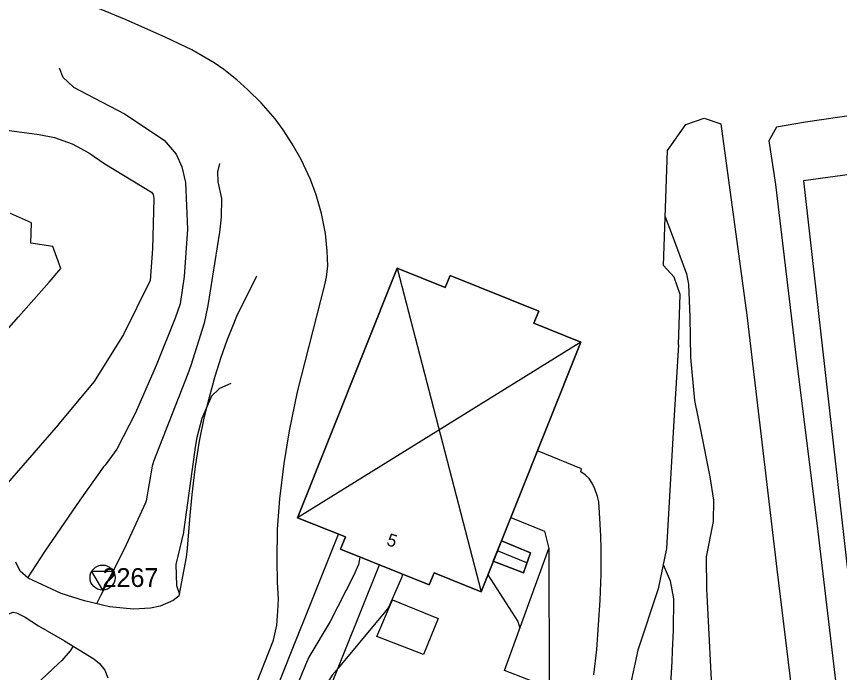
# Model space of a CAD drawing. Extents: x 67169 to 69652, y 20189 to 22818.
# Drawn here: x 69362.6 to 69428.4, y 21264.9 to 21317.2 of the extents above; entities that cross this region are included whole.
import ezdxf

# ---------------------------------------------------------------- set-up
doc = ezdxf.new("R2010")
doc.units = 0
for name, color, linetype in [('BYGGNAD_HUSLIV', 7, 'Continuous'), ('BYGGNAD_HUSLIV 11', 7, 'Continuous'), ('BYGGNADSSYMBOLER', 7, 'Continuous'), ('BYGGNADSSYMBOLER 30', 7, 'Continuous'), ('HOJDKURVOR_2014', 7, 'Continuous'), ('HOJDKURVOR_2014 5M', 7, 'Continuous'), ('Instruktioner', 7, 'Continuous'), ('MUR_STAKET', 7, 'Continuous'), ('MUR_STAKET_SYMBOL', 7, 'Continuous'), ('Std_Ritningsstämpel', 7, 'Continuous'), ('STOMPUNKTER', 7, 'Continuous'), ('STOMPUNKTER TEXT', 7, 'Continuous'), ('VAGAR 121', 7, 'Continuous'), ('VAGAR 123', 7, 'Continuous')]:
    doc.layers.add(name, color=color, linetype=linetype)

msp = doc.modelspace()

# ---------------------------------------------------------------- linework, layer by layer
at = {"layer": 'BYGGNAD_HUSLIV'}
for points in [[(69393.045, 21297.137), (69396.867, 21295.597), (69397.259, 21296.571), (69404.346, 21293.717), (69403.954, 21292.742), (69407.707, 21291.231), (69399.739, 21271.323), (69395.986, 21272.834), (69395.594, 21271.861), (69388.506, 21274.714), (69388.899, 21275.688), (69385.077, 21277.228), (69393.045, 21297.137)], [(69400.711, 21273.753), (69401.368, 21275.394), (69403.69, 21274.419), (69403.113, 21272.833), (69400.711, 21273.753)]]:
    msp.add_lwpolyline(points, dxfattribs=at)
at = {"layer": 'BYGGNAD_HUSLIV 11'}
msp.add_lwpolyline([(69393.045, 21297.137), (69396.867, 21295.597), (69397.259, 21296.571), (69404.346, 21293.717), (69403.954, 21292.742), (69407.707, 21291.231), (69399.739, 21271.323), (69395.986, 21272.834), (69395.594, 21271.861), (69388.506, 21274.714), (69388.899, 21275.688), (69385.077, 21277.228), (69393.045, 21297.137)], dxfattribs=at)
at = {"layer": 'BYGGNADSSYMBOLER'}
for p, q in [((69393.045, 21297.137), (69399.739, 21271.323)), ((69407.707, 21291.231), (69385.077, 21277.228)), ((69403.401, 21273.626), (69401.04, 21274.573))]:
    msp.add_line(p, q, dxfattribs=at)
at = {"layer": 'BYGGNADSSYMBOLER 30'}
for p, q in [((69393.045, 21297.137), (69399.739, 21271.323)), ((69407.707, 21291.231), (69385.077, 21277.228))]:
    msp.add_line(p, q, dxfattribs=at)
at = {"layer": 'HOJDKURVOR_2014'}
for points in [[(69366.062, 21313.148), (69366.332, 21312.38), (69367.183, 21311.587), (69368.875, 21310.704), (69371.275, 21309.469), (69374.422, 21307.369), (69375.396, 21306.253), (69375.858, 21305.221), (69376.147, 21303.984), (69376.289, 21300.262), (69376.042, 21296.479), (69375.707, 21294.299), (69375.323, 21293.164), (69373.805, 21289.375), (69372.142, 21285.594), (69370.649, 21282.69), (69369.713, 21281.421), (69369.603, 21281.289), (69367.704, 21278.629), (69364.915, 21274.561), (69363.536, 21272.425)], [(69378.863, 21305.507), (69378.681, 21304.824), (69378.719, 21304.04), (69379.016, 21302.704), (69378.993, 21301.226), (69378.841, 21300.023), (69377.914, 21294.162), (69377.639, 21292.766), (69376.567, 21289.372), (69376.315, 21288.705), (69373.596, 21281.719), (69373.464, 21281.331), (69373.004, 21278.561), (69372.954, 21278.402), (69371.228, 21274.711), (69369.385, 21271.032), (69369.027, 21270.352)], [(69379.75, 21287.952), (69378.854, 21287.534), (69378.205, 21286.934), (69377.45, 21285.136), (69377.054, 21283.621), (69376.915, 21282.849), (69376.856, 21282.461), (69375.98, 21276.098), (69375.969, 21276.054), (69375.358, 21273.493), (69375.429, 21271.806), (69375.669, 21271.128)], [(69390.056, 21274.09), (69389.939, 21273.486), (69389.547, 21272.582), (69387.675, 21268.953), (69385.976, 21266.085), (69385.71, 21265.48), (69383.133, 21259.153), (69382.74, 21258.152)], [(69414.284, 21273.49), (69414.846, 21272.202), (69415.096, 21270.761), (69415.066, 21268.26), (69414.999, 21266.593), (69414.956, 21265.759), (69414.698, 21261.223)], [(69400.282, 21272.679), (69402.666, 21268.945), (69402.835, 21268.423)], [(69367.175, 21266.967), (69366.936, 21266.605), (69366.257, 21265.822), (69366.009, 21265.58), (69363.704, 21263.443), (69362.278, 21262.161), (69359.337, 21259.705), (69357.821, 21258.53), (69354.449, 21255.997), (69353.343, 21255.257), (69350.982, 21254.075), (69348.891, 21253.425)]]:
    msp.add_lwpolyline(points, dxfattribs=at)
at = {"layer": 'HOJDKURVOR_2014 5M'}
for points in [[(69357.261, 21308.773), (69364.451, 21307.814), (69365.679, 21307.565), (69367.082, 21307.056), (69368.425, 21306.338), (69369.685, 21305.47), (69373.423, 21303.206), (69373.558, 21303.019), (69373.614, 21302.708), (69373.492, 21298.689), (69373.312, 21296.149), (69371.201, 21291.841), (69368.84, 21288.11), (69366.033, 21284.71), (69365.964, 21284.633), (69361.735, 21279.781)], [(69414.432, 21301.237), (69414.998, 21299.79), (69416.14, 21296.684), (69416.299, 21295.877), (69416.396, 21293.255), (69416.457, 21290.019), (69416.767, 21286.576), (69417.274, 21284.109), (69417.995, 21280.5), (69418.291, 21278.617), (69418.266, 21276.927), (69417.716, 21274.095), (69417.726, 21271.528), (69417.748, 21271.035), (69418.223, 21262.202)], [(69393.453, 21272.723), (69393.37, 21272.422), (69392.354, 21270.069), (69392.144, 21269.798), (69388.053, 21264.912), (69387.853, 21264.656), (69387.335, 21263.83), (69386.198, 21261.349), (69385.974, 21260.71), (69384.88, 21257.329)]]:
    msp.add_lwpolyline(points, dxfattribs=at)
at = {"layer": 'MUR_STAKET'}
for points in [[(69375.634, 21270.984), (69376.21, 21274.085), (69376.297, 21274.807), (69376.506, 21277.397), (69376.681, 21279.087), (69376.768, 21279.985), (69376.943, 21281.323), (69377.258, 21283.331), (69377.661, 21285.304), (69378.047, 21286.854), (69378.504, 21288.527), (69378.995, 21290.042), (69379.47, 21291.398), (69379.962, 21292.649), (69380.244, 21293.318), (69381.834, 21296.539)], [(69408.747, 21264.686), (69408.98, 21266.712), (69409.246, 21270.644), (69409.318, 21272.723), (69409.316, 21274.707), (69409.293, 21275.783), (69409.187, 21277.619), (69409.127, 21278.501), (69409.043, 21278.933), (69408.831, 21279.535), (69408.61, 21279.989), (69408.357, 21280.346), (69408.06, 21280.642), (69407.702, 21280.884), (69407.765, 21281.116), (69404.235, 21282.555)], [(69402.109, 21277.244), (69404.787, 21276.153), (69405.146, 21274.761), (69405.166, 21263.65)], [(69381.462, 21258.643), (69383.613, 21264.086), (69385.027, 21267.616), (69385.796, 21269.516), (69388.35, 21275.909)], [(69385.157, 21257.133), (69387.341, 21262.785), (69391.623, 21273.459)]]:
    msp.add_lwpolyline(points, dxfattribs=at)
at = {"layer": 'MUR_STAKET_SYMBOL'}
for p, q in [((69381.443, 21295.747), (69381.443, 21295.747)), ((69380.711, 21294.265), (69380.711, 21294.265)), ((69380.095, 21292.968), (69380.095, 21292.968)), ((69379.572, 21291.654), (69379.572, 21291.654)), ((69379.023, 21290.119), (69379.023, 21290.119)), ((69378.532, 21288.62), (69378.532, 21288.62)), ((69378.138, 21287.191), (69378.138, 21287.191)), ((69377.738, 21285.618), (69377.738, 21285.618)), ((69377.418, 21284.114), (69377.418, 21284.114)), ((69377.161, 21282.725), (69377.161, 21282.725)), ((69405.587, 21282.001), (69405.587, 21282.001)), ((69407.034, 21281.411), (69407.034, 21281.411)), ((69376.933, 21281.246), (69376.933, 21281.246)), ((69408.385, 21280.295), (69408.385, 21280.295)), ((69376.73, 21279.629), (69376.73, 21279.629)), ((69408.993, 21279.074), (69408.993, 21279.074)), ((69376.572, 21278.033), (69376.572, 21278.033)), ((69409.183, 21277.672), (69409.183, 21277.672)), ((69376.441, 21276.628), (69376.441, 21276.628)), ((69409.261, 21276.263), (69409.261, 21276.263)), ((69376.322, 21275.159), (69376.322, 21275.159)), ((69388.009, 21275.06), (69388.009, 21275.06)), ((69409.311, 21274.743), (69409.311, 21274.743)), ((69376.156, 21273.8), (69376.156, 21273.8)), ((69387.461, 21273.688), (69387.461, 21273.688)), ((69409.318, 21273.267), (69409.318, 21273.267)), ((69375.887, 21272.352), (69375.887, 21272.352)), ((69386.908, 21272.306), (69386.908, 21272.306)), ((69391.083, 21272.108), (69391.083, 21272.108)), ((69409.277, 21271.649), (69409.277, 21271.649)), ((69375.653, 21271.091), (69375.653, 21271.091)), ((69386.35, 21270.908), (69386.35, 21270.908)), ((69390.525, 21270.72), (69390.525, 21270.72)), ((69409.213, 21270.171), (69409.213, 21270.171)), ((69385.783, 21269.484), (69385.783, 21269.484)), ((69389.954, 21269.298), (69389.954, 21269.298)), ((69405.155, 21269.144), (69405.155, 21269.144)), ((69409.113, 21268.674), (69409.113, 21268.674)), ((69385.212, 21268.07), (69385.212, 21268.07)), ((69389.397, 21267.908), (69389.397, 21267.908)), ((69409.014, 21267.216), (69409.014, 21267.216)), ((69384.663, 21266.713), (69384.663, 21266.713)), ((69388.829, 21266.493), (69388.829, 21266.493)), ((69408.863, 21265.719), (69408.863, 21265.719)), ((69384.111, 21265.334), (69384.111, 21265.334)), ((69388.273, 21265.105), (69388.273, 21265.105))]:
    msp.add_line(p, q, dxfattribs=at)
at = {"layer": 'Std_Ritningsstämpel'}
for points in [[(69393.045, 21297.137), (69385.077, 21277.228), (69388.899, 21275.688), (69388.506, 21274.714), (69395.594, 21271.861), (69395.986, 21272.834), (69399.739, 21271.323), (69407.707, 21291.231), (69403.954, 21292.742), (69404.346, 21293.717), (69397.259, 21296.571), (69396.867, 21295.597)], [(69400.711, 21273.753), (69403.113, 21272.833), (69403.69, 21274.419), (69401.368, 21275.394)]]:
    msp.add_lwpolyline(points, close=True, dxfattribs=at)
at = {"layer": 'STOMPUNKTER'}
msp.add_lwpolyline([(69369.514, 21271.451), (69370.392, 21272.931), (69368.639, 21272.931)], close=True, dxfattribs=at)
msp.add_circle((69369.514, 21272.451), 1, dxfattribs=at)
at = {"layer": 'VAGAR 121'}
for points in [[(69379.822, 21258.929), (69383.159, 21267.446), (69383.43, 21268.647), (69383.52, 21269.757), (69383.564, 21270.732), (69383.495, 21272.092), (69383.448, 21273.837), (69383.491, 21276.307), (69383.671, 21278.732), (69384.009, 21281.566), (69384.436, 21284.15), (69385.069, 21287.278), (69387.259, 21295.802), (69387.395, 21296.436), (69387.508, 21297.32), (69387.461, 21298.499), (69387.324, 21299.904), (69386.983, 21301.513), (69386.573, 21303.008), (69386.119, 21304.231), (69385.37, 21305.818), (69384.667, 21307.063), (69383.94, 21308.197), (69383.305, 21309.057), (69382.176, 21310.341), (69381.11, 21311.372), (69380.226, 21312.165), (69379.194, 21313.002), (69378.434, 21313.523), (69377.8, 21313.919), (69376.633, 21314.575), (69374.58, 21315.548), (69371.395, 21316.973), (69369.275, 21317.844)], [(69429.852, 21309.408), (69430.351, 21304.992), (69429.94, 21304.717), (69425.48, 21304.106), (69430.55, 21259.186), (69435.055, 21259.627), (69435.319, 21259.215), (69434.195, 21246.773), (69431.808, 21226.862), (69431.598, 21226.403)], [(69402.109, 21277.244), (69404.787, 21276.153), (69405.146, 21274.761)], [(69392.658, 21270.678), (69396.317, 21269.192), (69395.147, 21266.318), (69391.417, 21267.752), (69392.658, 21270.678)]]:
    msp.add_lwpolyline(points, dxfattribs=at)
at = {"layer": 'VAGAR 123'}
for points in [[(69415.51, 21291.02), (69415.641, 21295.031), (69415.148, 21296.42), (69414.296, 21297.365), (69414.617, 21306.543), (69416.075, 21308.606), (69417.548, 21309.131), (69418.87, 21308.663), (69420.952, 21293.399), (69423.357, 21273.119), (69424.797, 21261.333), (69426.295, 21250.906), (69427.29, 21244.89), (69427.899, 21238.468), (69428.199, 21231.65), (69427.684, 21225.344)], [(69429.852, 21309.408), (69425.625, 21308.81), (69423.314, 21308.399), (69422.714, 21307.312), (69423.237, 21303.827), (69424.984, 21289.321), (69426.536, 21276.782), (69428.635, 21259.05), (69429.946, 21249.893), (69430.862, 21243.778), (69431.231, 21240.653), (69431.817, 21235.059), (69431.598, 21226.403)], [(69361.075, 21291.324), (69362.797, 21293.274), (69365.241, 21296.041), (69366.192, 21297.13), (69365.557, 21298.874), (69363.789, 21299.145), (69363.832, 21300.754), (69362.178, 21301.501)], [(69415.51, 21291.02), (69415.122, 21284.949), (69414.548, 21274.78), (69413.888, 21271.563), (69412.245, 21266.651), (69411.583, 21263.567), (69410.569, 21258.181), (69406.636, 21241.752)], [(69405.166, 21263.65), (69401.602, 21265.039), (69405.146, 21274.761)], [(69371.985, 21269.927), (69370.057, 21270.107), (69368.063, 21270.582), (69366.203, 21271.191), (69363.573, 21272.391), (69362.939, 21272.956), (69362.598, 21273.681)], [(69375.634, 21270.984), (69375.155, 21270.611), (69374.113, 21270.168), (69373.331, 21269.998), (69371.985, 21269.927)], [(69350.857, 21258.946), (69350.978, 21259.579), (69350.932, 21260.305), (69350.682, 21261.234), (69350.637, 21261.551), (69350.636, 21261.868), (69350.862, 21262.48), (69351.157, 21262.799), (69354.124, 21264.704), (69357.793, 21267.042), (69360.331, 21268.721), (69361.259, 21269.266), (69362.392, 21269.675), (69362.647, 21269.624), (69363.327, 21269.285), (69364.405, 21268.595), (69366.479, 21267.395), (69368.815, 21265.958), (69369.268, 21265.584), (69369.688, 21265.052), (69369.949, 21264.44)]]:
    msp.add_lwpolyline(points, dxfattribs=at)

# ---------------------------------------------------------------- texts
at = {"layer": 'Instruktioner'}
msp.add_text('5', height=1, rotation=341.61453, dxfattribs=at).set_placement((69392.127, 21275.065))
at = {"layer": 'STOMPUNKTER TEXT'}
msp.add_text('2267', height=1.5, dxfattribs=at).set_placement((69369.514, 21271.701))

doc.saveas('drawing.dxf')
